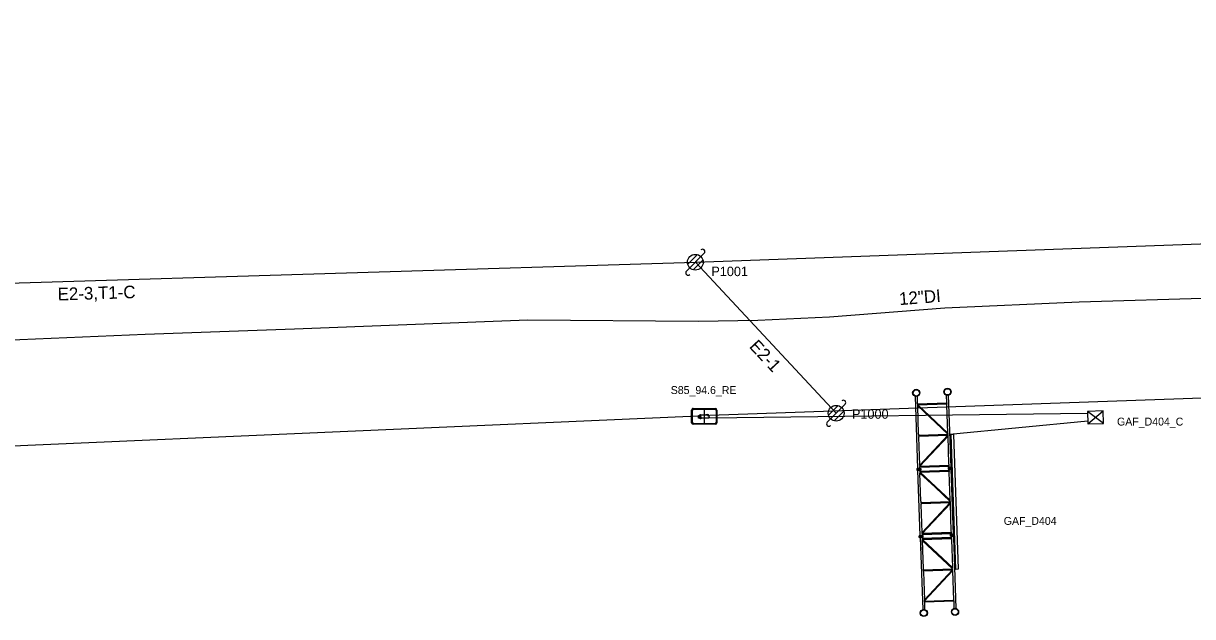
# Model space of a CAD drawing. Extents: x 1614474 to 1865144, y 1098877 to 1212550.
# Drawn here: x 1810361.4 to 1810731.8, y 1190121.1 to 1190308.9 of the extents above; entities that cross this region are included whole.
import ezdxf

# ---------------------------------------------------------------- set-up
doc = ezdxf.new("R2010")
doc.units = 0
for name, color, linetype in [('BFUSER_CABINET', 7, 'Continuous'), ('BFUSER_CABINETNAME', 7, 'Continuous'), ('BFUSER_DUCTENCLOSURE', 7, 'Continuous'), ('BFUSER_FIBERNODE', 7, 'Continuous'), ('BFUSER_FIBERNODENAME', 7, 'Continuous'), ('BFUSER_FIBERSPAN', 7, 'Continuous'), ('BFUSER_FIBERSPLICEENCLOSURE', 7, 'Continuous'), ('BFUSER_FIBERSPLICEENCLOSURENAME', 7, 'Continuous'), ('RD_EX_SU_H2O', 7, 'Continuous'), ('RD_EX_SU_Ovhd', 7, 'Continuous'), ('RD_EX_SU_Pole', 7, 'Continuous'), ('RD_EX_SU_TX_H2O', 7, 'Continuous'), ('RD_EX_SU_TX_Pole', 7, 'Continuous')]:
    doc.layers.add(name, color=color, linetype=linetype)

msp = doc.modelspace()

# ---------------------------------------------------------------- linework, layer by layer
at = {"layer": 'BFUSER_CABINET'}
for p, q in [((1810703.52, 1190182.25), (1810698.41, 1190186.11)), ((1810698.52, 1190182.11), (1810703.41, 1190186.25))]:
    msp.add_line(p, q, dxfattribs=at)
msp.add_lwpolyline([(1810703.52, 1190182.25), (1810703.41, 1190186.25), (1810698.41, 1190186.11), (1810698.52, 1190182.11)], close=True, dxfattribs=at)
at = {"layer": 'BFUSER_DUCTENCLOSURE'}
msp.add_line((1810577.06, 1190186.75), (1810577.06, 1190182.24), dxfattribs=at)
for points in [[(1810573.06, 1190182.5), (1810573.06, 1190186.5)], [(1810573.29, 1190182.64), (1810573.29, 1190186.35)], [(1810573.56, 1190187), (1810580.56, 1190187)], [(1810573.69, 1190186.75), (1810580.43, 1190186.75)], [(1810580.83, 1190186.35), (1810580.83, 1190182.64)], [(1810581.06, 1190186.5), (1810581.06, 1190182.5)], [(1810580.56, 1190182), (1810573.56, 1190182)], [(1810573.69, 1190182.24), (1810580.43, 1190182.24)]]:
    msp.add_lwpolyline(points, dxfattribs=at)
for centre, radius, start, end in [((1810573.56, 1190186.5), 0.5, 90.0004, 180.0004), ((1810573.69, 1190186.35), 0.4, 90.0004, 180.0004), ((1810580.43, 1190186.35), 0.4, 0.0004, 90.0004), ((1810580.56, 1190186.5), 0.5, 0.0004, 90.0004), ((1810573.56, 1190182.5), 0.5, 180.0004, 270.0004), ((1810573.69, 1190182.64), 0.4, 180.0004, 270.0004), ((1810580.43, 1190182.64), 0.4, 270.0004, 0.0004), ((1810580.56, 1190182.5), 0.5, 270.0004, 0.0004)]:
    msp.add_arc(centre, radius, start, end, dxfattribs=at)
at = {"layer": 'BFUSER_FIBERNODE'}
for p, q in [((1810644.72, 1190167.99), (1810643.94, 1190190.82)), ((1810644.64, 1190188.49), (1810644.56, 1190190.84)), ((1810653.91, 1190188.81), (1810653.83, 1190191.16)), ((1810655.24, 1190168.35), (1810654.45, 1190191.18)), ((1810644.64, 1190188.49), (1810653.91, 1190188.81)), ((1810644.65, 1190188.18), (1810653.92, 1190188.5)), ((1810644.66, 1190187.84), (1810654.23, 1190178.91)), ((1810644.96, 1190178.93), (1810644.66, 1190187.84)), ((1810644.67, 1190188.18), (1810654.24, 1190179.25)), ((1810654.24, 1190179.25), (1810653.94, 1190188.16)), ((1810644.98, 1190178.59), (1810654.25, 1190178.91)), ((1810644.99, 1190178.28), (1810654.26, 1190178.6)), ((1810645.3, 1190169.03), (1810645, 1190177.95)), ((1810654.24, 1190178.6), (1810645.3, 1190169.03)), ((1810645.34, 1190168.7), (1810654.28, 1190178.27)), ((1810654.58, 1190169.35), (1810654.28, 1190178.27)), ((1810645.32, 1190168.7), (1810654.59, 1190169.02)), ((1810645.33, 1190168.39), (1810654.6, 1190168.71)), ((1810654.62, 1190168.33), (1810654.6, 1190168.71)), ((1810644.41, 1190167.98), (1810645.65, 1190168.02)), ((1810644.41, 1190167.98), (1810644.42, 1190167.72)), ((1810644.42, 1190167.72), (1810645.66, 1190167.76)), ((1810644.42, 1190167.72), (1810645.66, 1190167.76)), ((1810644.42, 1190167.72), (1810644.43, 1190167.46)), ((1810644.43, 1190167.46), (1810645.67, 1190167.5)), ((1810645.34, 1190168.01), (1810644.72, 1190167.99)), ((1810644.73, 1190167.73), (1810645.35, 1190167.75)), ((1810645.35, 1190167.75), (1810644.73, 1190167.73)), ((1810644.74, 1190167.47), (1810645.36, 1190167.49)), ((1810645.45, 1190146.74), (1810644.74, 1190167.47)), ((1810645.02, 1190167.98), (1810645.03, 1190168)), ((1810645.03, 1190167.73), (1810645.04, 1190167.74)), ((1810645.34, 1190168.01), (1810645.33, 1190168.38)), ((1810645.37, 1190167.19), (1810645.36, 1190167.49)), ((1810645.37, 1190167.18), (1810654.65, 1190167.5)), ((1810645.38, 1190166.88), (1810654.66, 1190167.2)), ((1810650.19, 1190162.06), (1810645.39, 1190166.54)), ((1810645.7, 1190157.63), (1810645.39, 1190166.53)), ((1810650.36, 1190162.25), (1810645.41, 1190166.88)), ((1810645.65, 1190168.02), (1810645.66, 1190167.76)), ((1810645.66, 1190167.76), (1810645.67, 1190167.5)), ((1810654.31, 1190168.32), (1810655.55, 1190168.36)), ((1810654.31, 1190168.32), (1810654.32, 1190168.06)), ((1810654.32, 1190168.06), (1810655.55, 1190168.1)), ((1810654.32, 1190168.06), (1810655.55, 1190168.1)), ((1810654.32, 1190168.06), (1810654.33, 1190167.8)), ((1810654.33, 1190167.8), (1810655.56, 1190167.84)), ((1810655.24, 1190168.35), (1810654.62, 1190168.33)), ((1810654.63, 1190168.07), (1810655.24, 1190168.09)), ((1810655.24, 1190168.09), (1810654.63, 1190168.07)), ((1810654.63, 1190167.81), (1810655.25, 1190167.83)), ((1810654.65, 1190167.5), (1810654.63, 1190167.81)), ((1810654.97, 1190157.95), (1810654.67, 1190166.87)), ((1810654.92, 1190168.32), (1810654.93, 1190168.34)), ((1810654.92, 1190168.07), (1810654.94, 1190168.08)), ((1810655.97, 1190147.1), (1810655.25, 1190167.82)), ((1810655.55, 1190168.36), (1810655.55, 1190168.1)), ((1810655.55, 1190168.1), (1810655.56, 1190167.84)), ((1810654.96, 1190157.61), (1810650.19, 1190162.06)), ((1810654.97, 1190157.95), (1810650.36, 1190162.25)), ((1810645.71, 1190157.29), (1810654.99, 1190157.61)), ((1810645.72, 1190156.98), (1810655, 1190157.3)), ((1810646.04, 1190147.74), (1810645.73, 1190156.65)), ((1810654.97, 1190157.3), (1810646.04, 1190147.74)), ((1810655.01, 1190156.97), (1810646.07, 1190147.4)), ((1810655.31, 1190148.05), (1810655.01, 1190156.97)), ((1810646.38, 1190146.78), (1810645.14, 1190146.73)), ((1810645.14, 1190146.72), (1810646.38, 1190146.76)), ((1810645.15, 1190146.48), (1810645.14, 1190146.73)), ((1810645.15, 1190146.46), (1810645.14, 1190146.72)), ((1810646.39, 1190146.52), (1810645.15, 1190146.48)), ((1810646.39, 1190146.52), (1810645.15, 1190146.48)), ((1810645.15, 1190146.46), (1810646.39, 1190146.51)), ((1810645.15, 1190146.46), (1810646.39, 1190146.51)), ((1810645.16, 1190146.22), (1810645.15, 1190146.48)), ((1810645.16, 1190146.21), (1810645.15, 1190146.46)), ((1810646.07, 1190146.76), (1810645.45, 1190146.74)), ((1810645.45, 1190146.73), (1810646.07, 1190146.75)), ((1810646.08, 1190146.51), (1810645.46, 1190146.49)), ((1810645.46, 1190146.49), (1810646.08, 1190146.51)), ((1810645.46, 1190146.47), (1810646.08, 1190146.5)), ((1810646.08, 1190146.5), (1810645.46, 1190146.47)), ((1810645.76, 1190146.5), (1810645.77, 1190146.48)), ((1810645.78, 1190146.51), (1810645.77, 1190146.5)), ((1810655.32, 1190147.72), (1810646.05, 1190147.4)), ((1810646.05, 1190147.36), (1810655.33, 1190147.68)), ((1810655.34, 1190147.4), (1810646.06, 1190147.08)), ((1810646.06, 1190147.07), (1810655.34, 1190147.39)), ((1810646.06, 1190147.08), (1810646.07, 1190146.76)), ((1810646.06, 1190147.05), (1810646.07, 1190146.75)), ((1810646.39, 1190146.52), (1810646.38, 1190146.78)), ((1810646.39, 1190146.51), (1810646.38, 1190146.76)), ((1810646.4, 1190146.26), (1810646.39, 1190146.52)), ((1810646.4, 1190146.25), (1810646.39, 1190146.51)), ((1810656.27, 1190147.12), (1810655.04, 1190147.07)), ((1810655.04, 1190147.06), (1810656.27, 1190147.1)), ((1810655.05, 1190146.81), (1810655.04, 1190147.07)), ((1810655.05, 1190146.8), (1810655.04, 1190147.06)), ((1810656.28, 1190146.86), (1810655.05, 1190146.81)), ((1810656.28, 1190146.86), (1810655.05, 1190146.81)), ((1810655.05, 1190146.8), (1810656.28, 1190146.85)), ((1810655.05, 1190146.8), (1810656.28, 1190146.85)), ((1810655.05, 1190146.56), (1810655.05, 1190146.81)), ((1810655.06, 1190146.55), (1810655.05, 1190146.8)), ((1810656.29, 1190146.6), (1810655.05, 1190146.56)), ((1810655.06, 1190146.55), (1810656.29, 1190146.59)), ((1810655.34, 1190147.39), (1810655.35, 1190147.07)), ((1810655.34, 1190147.38), (1810655.35, 1190147.08)), ((1810655.97, 1190147.1), (1810655.35, 1190147.08)), ((1810655.35, 1190147.07), (1810655.97, 1190147.09)), ((1810655.97, 1190146.85), (1810655.36, 1190146.83)), ((1810655.36, 1190146.83), (1810655.97, 1190146.85)), ((1810655.36, 1190146.81), (1810655.97, 1190146.84)), ((1810655.97, 1190146.84), (1810655.36, 1190146.81)), ((1810655.36, 1190146.57), (1810655.98, 1190146.59)), ((1810655.98, 1190146.58), (1810655.36, 1190146.56)), ((1810655.36, 1190146.57), (1810655.38, 1190146.2)), ((1810655.36, 1190146.56), (1810655.38, 1190146.17)), ((1810655.65, 1190146.84), (1810655.67, 1190146.82)), ((1810655.68, 1190146.85), (1810655.66, 1190146.84)), ((1810655.66, 1190146.58), (1810655.67, 1190146.57)), ((1810655.68, 1190146.59), (1810655.67, 1190146.58)), ((1810655.98, 1190146.59), (1810656.12, 1190142.52)), ((1810655.98, 1190146.58), (1810656.77, 1190123.72)), ((1810656.28, 1190146.86), (1810656.27, 1190147.12)), ((1810656.28, 1190146.85), (1810656.27, 1190147.1)), ((1810656.29, 1190146.6), (1810656.28, 1190146.86)), ((1810656.29, 1190146.59), (1810656.28, 1190146.85)), ((1810646.4, 1190146.26), (1810645.16, 1190146.22)), ((1810645.16, 1190146.21), (1810646.4, 1190146.25)), ((1810645.47, 1190146.23), (1810646.09, 1190146.25)), ((1810646.09, 1190146.24), (1810645.47, 1190146.22)), ((1810645.47, 1190146.23), (1810645.61, 1190142.16)), ((1810645.47, 1190146.22), (1810646.25, 1190123.36)), ((1810645.77, 1190146.24), (1810645.78, 1190146.23)), ((1810645.79, 1190146.25), (1810645.78, 1190146.24)), ((1810646.09, 1190146.25), (1810646.1, 1190145.87)), ((1810646.09, 1190146.24), (1810646.1, 1190145.87)), ((1810655.38, 1190146.18), (1810646.1, 1190145.87)), ((1810646.1, 1190145.85), (1810655.38, 1190146.17)), ((1810655.39, 1190145.88), (1810646.11, 1190145.56)), ((1810646.11, 1190145.55), (1810655.39, 1190145.87)), ((1810646.12, 1190145.21), (1810646.43, 1190136.3)), ((1810655.69, 1190136.28), (1810646.12, 1190145.21)), ((1810646.12, 1190145.2), (1810646.23, 1190142.18)), ((1810646.14, 1190145.55), (1810655.71, 1190136.62)), ((1810655.4, 1190145.53), (1810655.71, 1190136.62)), ((1810655.4, 1190145.52), (1810655.5, 1190142.5)), ((1810646.44, 1190135.96), (1810655.72, 1190136.28)), ((1810646.45, 1190135.65), (1810655.73, 1190135.97)), ((1810646.46, 1190135.31), (1810646.77, 1190126.4)), ((1810646.77, 1190126.4), (1810655.7, 1190135.97)), ((1810646.81, 1190126.07), (1810655.74, 1190135.63)), ((1810655.74, 1190135.63), (1810656.06, 1190126.38)), ((1810646.78, 1190126.06), (1810656.06, 1190126.38)), ((1810646.79, 1190125.76), (1810656.07, 1190126.07)), ((1810646.79, 1190125.76), (1810646.87, 1190123.38)), ((1810656.07, 1190126.07), (1810656.15, 1190123.7))]:
    msp.add_line(p, q, dxfattribs=at)
msp.add_lwpolyline([(1810655.19, 1190178.76), (1810656.65, 1190136.19), (1810657.57, 1190136.22), (1810656.11, 1190178.8)], close=True, dxfattribs=at)
for centre, radius in [((1810644.21, 1190191.95), 1.14), ((1810644.21, 1190191.95), 0.993), ((1810654.1, 1190192.29), 1.14), ((1810654.1, 1190192.29), 0.993), ((1810646.6, 1190122.27), 1.14), ((1810646.6, 1190122.28), 0.993), ((1810656.5, 1190122.61), 1.14), ((1810656.5, 1190122.62), 0.993)]:
    msp.add_circle(centre, radius, dxfattribs=at)
for centre, radius, start, end in [((1810644.91, 1190188.34), 0.309, 151.9663, 211.9663), ((1810644.97, 1190188.02), 0.363, 154.3307, 209.6018), ((1810653.65, 1190188.64), 0.309, 331.9663, 31.9663), ((1810653.61, 1190188.32), 0.363, 334.3307, 29.6018), ((1810645.29, 1190178.77), 0.363, 154.3307, 209.6018), ((1810645.25, 1190178.45), 0.309, 151.9663, 211.9663), ((1810645.31, 1190178.13), 0.363, 154.3307, 209.6018), ((1810653.93, 1190179.07), 0.363, 334.3307, 29.6018), ((1810653.99, 1190178.75), 0.309, 331.9663, 31.9663), ((1810653.95, 1190178.42), 0.363, 334.3307, 29.6018), ((1810645.63, 1190168.88), 0.363, 154.3307, 209.6018), ((1810645.59, 1190168.55), 0.309, 151.9663, 211.6866), ((1810654.27, 1190169.17), 0.363, 334.3307, 29.6018), ((1810654.33, 1190168.85), 0.309, 329.2645, 31.9663), ((1810645.64, 1190167.04), 0.309, 154.0685, 211.9663), ((1810645.71, 1190166.72), 0.363, 154.3307, 209.6018), ((1810654.38, 1190167.34), 0.309, 331.9663, 31.3174), ((1810654.34, 1190167.02), 0.363, 334.3307, 29.6018), ((1810646.02, 1190157.47), 0.363, 154.3307, 209.6018), ((1810654.66, 1190157.77), 0.363, 334.3307, 29.6018), ((1810654.72, 1190157.45), 0.309, 331.9663, 31.9663), ((1810645.98, 1190157.15), 0.309, 151.9663, 211.9663), ((1810646.05, 1190156.83), 0.363, 154.3307, 209.6018), ((1810654.68, 1190157.12), 0.363, 334.3307, 29.6018), ((1810646.36, 1190147.58), 0.363, 154.3308, 209.6018), ((1810646.36, 1190147.54), 0.363, 154.3308, 209.6018), ((1810646.32, 1190147.25), 0.309, 151.9663, 213.5055), ((1810646.32, 1190147.22), 0.309, 151.9663, 209.8641), ((1810655, 1190147.87), 0.363, 334.3308, 29.6018), ((1810655, 1190147.84), 0.363, 334.3308, 29.6018), ((1810655.06, 1190147.55), 0.309, 330.4231, 31.9663), ((1810655.06, 1190147.52), 0.309, 332.6151, 31.9663), ((1810646.37, 1190145.72), 0.309, 149.2645, 211.9663), ((1810646.37, 1190145.71), 0.309, 152.2459, 211.9663), ((1810646.44, 1190145.4), 0.363, 154.3307, 209.6018), ((1810646.44, 1190145.39), 0.363, 154.3308, 209.6018), ((1810655.12, 1190146.01), 0.309, 331.9663, 34.6681), ((1810655.11, 1190146.02), 0.309, 331.9663, 31.6866), ((1810655.07, 1190145.7), 0.363, 334.3307, 29.6018), ((1810655.07, 1190145.69), 0.363, 334.3308, 29.6018), ((1810646.76, 1190136.14), 0.363, 154.3308, 209.6018), ((1810646.71, 1190135.82), 0.309, 151.9663, 211.9663), ((1810646.78, 1190135.49), 0.363, 154.3308, 209.6018), ((1810655.39, 1190136.44), 0.363, 334.3308, 29.6018), ((1810655.45, 1190136.12), 0.309, 331.9663, 31.9663), ((1810655.41, 1190135.79), 0.363, 334.3308, 29.6018), ((1810647.1, 1190126.24), 0.363, 154.3308, 209.6018), ((1810647.05, 1190125.92), 0.309, 151.9663, 211.9663), ((1810655.79, 1190126.22), 0.309, 331.9663, 31.9663)]:
    msp.add_arc(centre, radius, start, end, dxfattribs=at)
at = {"layer": 'BFUSER_FIBERSPAN'}
for p, q in [((1809476.93, 1190136.61), (1810575.1, 1190184.71)), ((1810578.79, 1190184.1), (1810698.44, 1190185.51)), ((1810654.85, 1190178.84), (1810698.58, 1190183.07))]:
    msp.add_line(p, q, dxfattribs=at)
msp.add_lwpolyline([(1810578.78, 1190184.92), (1812435.06, 1190250.22), (1812539.61, 1190260.56), (1812620.02, 1190277.93), (1812674.32, 1190298.05), (1812789.69, 1190276.78), (1813013.78, 1190308.92)], dxfattribs=at)
at = {"layer": 'BFUSER_FIBERSPLICEENCLOSURE'}
for p, q in [((1810575.25, 1190184.75), (1810575.26, 1190184.75)), ((1810575.25, 1190184.62), (1810575.25, 1190184.75)), ((1810575.26, 1190184.62), (1810575.25, 1190184.62)), ((1810575.25, 1190184.53), (1810575.27, 1190184.53)), ((1810575.26, 1190184.41), (1810575.25, 1190184.53)), ((1810575.26, 1190184.77), (1810575.62, 1190184.78)), ((1810575.27, 1190184.6), (1810575.26, 1190184.77)), ((1810575.26, 1190184.75), (1810575.26, 1190184.62)), ((1810575.27, 1190184.41), (1810575.26, 1190184.41)), ((1810575.26, 1190184.33), (1810575.28, 1190184.33)), ((1810575.28, 1190183.94), (1810575.26, 1190184.33)), ((1810575.63, 1190184.62), (1810575.27, 1190184.6)), ((1810575.27, 1190184.55), (1810575.63, 1190184.57)), ((1810575.27, 1190184.39), (1810575.27, 1190184.55)), ((1810575.27, 1190184.53), (1810575.27, 1190184.41)), ((1810575.64, 1190184.4), (1810575.27, 1190184.39)), ((1810575.28, 1190184.35), (1810575.63, 1190184.37)), ((1810575.3, 1190183.92), (1810575.28, 1190184.35)), ((1810575.28, 1190184.33), (1810575.29, 1190183.94)), ((1810575.29, 1190183.94), (1810575.28, 1190183.94)), ((1810575.66, 1190183.94), (1810575.3, 1190183.92)), ((1810575.62, 1190184.62), (1810575.62, 1190184.56)), ((1810575.62, 1190184.4), (1810575.68, 1190183.92)), ((1810575.69, 1190183.86), (1810575.64, 1190184.95)), ((1810575.64, 1190184.93), (1810575.75, 1190184.93)), ((1810575.69, 1190183.88), (1810575.64, 1190184.93)), ((1810575.79, 1190183.88), (1810575.69, 1190183.88)), ((1810575.74, 1190185.09), (1810575.9, 1190185.1)), ((1810575.8, 1190183.76), (1810575.74, 1190185.09)), ((1810575.75, 1190184.93), (1810575.79, 1190183.88)), ((1810575.96, 1190183.77), (1810575.8, 1190183.76)), ((1810575.9, 1190185.1), (1810575.96, 1190183.77)), ((1810575.91, 1190184.99), (1810578.08, 1190185.09)), ((1810575.91, 1190184.93), (1810578.09, 1190185.02)), ((1810578.49, 1190184.05), (1810575.95, 1190183.94)), ((1810578.49, 1190183.99), (1810575.95, 1190183.87)), ((1810576.32, 1190185.1), (1810576.3, 1190185.1)), ((1810576.3, 1190185.1), (1810576.3, 1190185.01)), ((1810576.3, 1190185.01), (1810576.33, 1190185.01)), ((1810576.33, 1190185.01), (1810576.32, 1190185.1)), ((1810576.64, 1190185.12), (1810576.62, 1190185.12)), ((1810576.62, 1190185.12), (1810576.62, 1190185.03)), ((1810576.62, 1190185.03), (1810576.64, 1190185.03)), ((1810576.64, 1190185.03), (1810576.64, 1190185.12)), ((1810577.45, 1190185.15), (1810577.42, 1190185.15)), ((1810577.42, 1190185.15), (1810577.43, 1190185.06)), ((1810577.43, 1190185.06), (1810577.45, 1190185.06)), ((1810577.45, 1190185.06), (1810577.45, 1190185.15)), ((1810577.77, 1190185.17), (1810577.74, 1190185.17)), ((1810577.74, 1190185.17), (1810577.75, 1190185.08)), ((1810577.75, 1190185.08), (1810577.77, 1190185.08)), ((1810577.77, 1190185.08), (1810577.77, 1190185.17)), ((1810578.09, 1190185.02), (1810578.09, 1190184.89)), ((1810578.15, 1190185.02), (1810578.16, 1190184.89)), ((1810578.23, 1190184.83), (1810578.46, 1190184.84)), ((1810578.24, 1190184.76), (1810578.46, 1190184.77)), ((1810578.46, 1190184.77), (1810578.49, 1190184.05)), ((1810578.53, 1190184.77), (1810578.56, 1190184.06))]:
    msp.add_line(p, q, dxfattribs=at)
for centre, radius, start, end in [((1810575.62, 1190184.81), 0.0265, 272.5068, 3.1971), ((1810575.63, 1190184.59), 0.0265, 1.8166, 92.5068), ((1810575.63, 1190184.59), 0.0265, 272.5068, 3.1971), ((1810575.64, 1190184.38), 0.0265, 1.8166, 92.5068), ((1810575.66, 1190183.91), 0.0265, 1.8166, 92.5068), ((1810578.09, 1190185.02), 0.0694, 2.5068, 92.5068), ((1810578.23, 1190184.9), 0.139, 182.5068, 272.5068), ((1810578.13, 1190184.65), 0.42, 21.389, 89.5138), ((1810578.13, 1190184.65), 0.392, 27.5528, 86.4646), ((1810578.23, 1190184.9), 0.0694, 182.5068, 272.5068), ((1810578.46, 1190184.77), 0.0694, 2.4585, 92.5068), ((1810578.49, 1190184.05), 0.0694, 272.5068, 2.4585), ((1810577.77, 1190184.38), 0.857, 334.5174, 27.3501)]:
    msp.add_arc(centre, radius, start, end, dxfattribs=at)
at = {"layer": 'RD_EX_SU_H2O'}
for points in [[(1810575.17, 1190214.64), (1810594, 1190215), (1810616.7, 1190215.99), (1810653.22, 1190218.84), (1810695.85, 1190220.76), (1810738.35, 1190222.04), (1810784.17, 1190223.81), (1810825.15, 1190225.11), (1810867.29, 1190226.82), (1810891.53, 1190226.72), (1810955.86, 1190230.25), (1810999.49, 1190231.58), (1811043.25, 1190233.5), (1811086.58, 1190235.09)], [(1809591.04, 1190181.32), (1809610.39, 1190182.17), (1809696.97, 1190185.67), (1809786.87, 1190188.66), (1809883.54, 1190192.41), (1809933.92, 1190194.51), (1810049.07, 1190198.52), (1810146.27, 1190201.48), (1810237.73, 1190204.86), (1810335.34, 1190207.78), (1810399.91, 1190210.57), (1810447.22, 1190212.22), (1810521.22, 1190215.05), (1810575.17, 1190214.64)]]:
    msp.add_lwpolyline(points, dxfattribs=at)
at = {"layer": 'RD_EX_SU_Ovhd'}
for p, q in [((1810574.24, 1190233.31), (1810934.49, 1190246.37)), ((1810212.63, 1190222.37), (1810574.24, 1190233.31)), ((1810574.24, 1190233.31), (1810618.85, 1190185.51))]:
    msp.add_line(p, q, dxfattribs=at)
at = {"layer": 'RD_EX_SU_Pole'}
for p, q in [((1810571.83, 1190232.66), (1810574.89, 1190235.73)), ((1810576.01, 1190235.08), (1810577.07, 1190236.14)), ((1810571.41, 1190230.48), (1810572.47, 1190231.54)), ((1810572.47, 1190231.54), (1810576.01, 1190235.08)), ((1810573.59, 1190230.9), (1810576.65, 1190233.96)), ((1810616.43, 1190184.86), (1810619.49, 1190187.92)), ((1810617.08, 1190183.74), (1810620.61, 1190187.28)), ((1810620.61, 1190187.28), (1810621.67, 1190188.34)), ((1810616.02, 1190182.68), (1810617.08, 1190183.74)), ((1810618.2, 1190183.09), (1810621.26, 1190186.15))]:
    msp.add_line(p, q, dxfattribs=at)
for centre in [(1810574.24, 1190233.31), (1810618.85, 1190185.51)]:
    msp.add_circle(centre, 2.5, dxfattribs=at)
for centre, start, end in [((1810576.54, 1190236.67), 315, 135), ((1810571.94, 1190229.95), 135, 315), ((1810621.14, 1190188.87), 315, 135), ((1810616.55, 1190182.15), 135, 315)]:
    msp.add_arc(centre, 0.75, start, end, dxfattribs=at)

# ---------------------------------------------------------------- texts
at = {"layer": 'BFUSER_CABINETNAME'}
msp.add_text('GAF_D404_C', height=2.5, rotation=359.9996, dxfattribs=at).set_placement((1810707.81, 1190181.61))
at = {"layer": 'BFUSER_FIBERNODENAME'}
msp.add_text('GAF_D404', height=2.5, rotation=359.9991, dxfattribs=at).set_placement((1810671.93, 1190150.17))
at = {"layer": 'BFUSER_FIBERSPLICEENCLOSURENAME'}
msp.add_text('S85_94.6_RE', height=2.5, rotation=359.9998, dxfattribs=at).set_placement((1810566.44, 1190191.59))
at = {"layer": 'RD_EX_SU_Ovhd'}
for s, rotation, p in [('E2-3,T1-C', 1.7327, (1810372.29, 1190221.2)), ('E2-1', 313.0183, (1810591.09, 1190206.46))]:
    msp.add_text(s, height=4, rotation=rotation, dxfattribs=at).set_placement(p)
at = {"layer": 'RD_EX_SU_TX_H2O'}
msp.add_text('12"DI', height=4, rotation=4.4549, dxfattribs=at).set_placement((1810638.94, 1190219.73))
at = {"layer": 'RD_EX_SU_TX_Pole'}
for s, p in [('P1001', (1810579.31, 1190228.91)), ('P1000', (1810623.84, 1190183.76))]:
    msp.add_text(s, height=3, dxfattribs=at).set_placement(p)

doc.saveas('drawing.dxf')
